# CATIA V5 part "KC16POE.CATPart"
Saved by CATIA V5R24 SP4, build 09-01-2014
Part number: KC16_AssiemeCompleto
Source: Unknown
Bounding box of the stored display mesh (mm): x 152.513 to 747.492, y 129.501 to 599, z 1609.5 to 2811.996
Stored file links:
  C:\Users\gianluca.diodoro\Desktop\Cappe 3D\KC16POE.CATPart
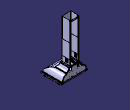
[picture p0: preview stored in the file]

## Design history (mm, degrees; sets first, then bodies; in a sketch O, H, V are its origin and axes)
Set1
  DatumSurface1 to DatumSurface402 "MANIFOLD_SOLID_BREP #451689"
Body1 "MANIFOLD_SOLID_BREP #44438" (main body)
  Solid1: solid without history
Body2 "MANIFOLD_SOLID_BREP #45255"
  Solid2: solid without history
Body3 "MANIFOLD_SOLID_BREP #57676"
  Solid3: solid without history
Body4 "MANIFOLD_SOLID_BREP #70097"
  Solid4: solid without history
Body5 "MANIFOLD_SOLID_BREP #70739"
  Solid5: solid without history
Body6 "MANIFOLD_SOLID_BREP #72519"
  Solid6: solid without history
Body7 "MANIFOLD_SOLID_BREP #73161"
  Solid7: solid without history
Body8 "MANIFOLD_SOLID_BREP #74941"
  Solid8: solid without history
Body9 "MANIFOLD_SOLID_BREP #89080"
  Solid9: solid without history
Body10 "MANIFOLD_SOLID_BREP #103211"
  Solid10: solid without history
Body11 "MANIFOLD_SOLID_BREP #106813"
  Solid11: solid without history
Body12 "MANIFOLD_SOLID_BREP #110415"
  Solid12: solid without history
Body13 "MANIFOLD_SOLID_BREP #133857"
  Solid13: solid without history
Body14 "MANIFOLD_SOLID_BREP #133987"
  Solid14: solid without history
Body15 "MANIFOLD_SOLID_BREP #140974"
  Solid15: solid without history
Body16 "MANIFOLD_SOLID_BREP #141441"
  Solid16: solid without history
Body17 "MANIFOLD_SOLID_BREP #141908"
  Solid17: solid without history
Body18 "MANIFOLD_SOLID_BREP #142375"
  Solid18: solid without history
Body19 "MANIFOLD_SOLID_BREP #142842"
  Solid19: solid without history
Body20 "MANIFOLD_SOLID_BREP #152109"
  Solid20: solid without history
Body21 "MANIFOLD_SOLID_BREP #152209"
  Solid21: solid without history
Body22 "MANIFOLD_SOLID_BREP #153280"
  Solid22: solid without history
Body23 "MANIFOLD_SOLID_BREP #154351"
  Solid23: solid without history
Body24 "MANIFOLD_SOLID_BREP #154854"
  Solid24: solid without history
Body25 "MANIFOLD_SOLID_BREP #155589"
  Solid25: solid without history
Body26 "MANIFOLD_SOLID_BREP #156092"
  Solid26: solid without history
Body27 "MANIFOLD_SOLID_BREP #156827"
  Solid27: solid without history
Body28 "MANIFOLD_SOLID_BREP #157562"
  Solid28: solid without history
Body29 "MANIFOLD_SOLID_BREP #158065"
  Solid29: solid without history
Body30 "MANIFOLD_SOLID_BREP #158800"
  Solid30: solid without history
Body31 "MANIFOLD_SOLID_BREP #159303"
  Solid31: solid without history
Body32 "MANIFOLD_SOLID_BREP #160374"
  Solid32: solid without history
Body33 "MANIFOLD_SOLID_BREP #161445"
  Solid33: solid without history
Body34 "MANIFOLD_SOLID_BREP #161545"
  Solid34: solid without history
Body35 "MANIFOLD_SOLID_BREP #162048"
  Solid35: solid without history
Body36 "MANIFOLD_SOLID_BREP #163071"
  Solid36: solid without history
Body37 "MANIFOLD_SOLID_BREP #164094"
  Solid37: solid without history
Body38 "MANIFOLD_SOLID_BREP #165117"
  Solid38: solid without history
Body39 "MANIFOLD_SOLID_BREP #166140"
  Solid39: solid without history
Body40 "MANIFOLD_SOLID_BREP #167163"
  Solid40: solid without history
Body41 "MANIFOLD_SOLID_BREP #168186"
  Solid41: solid without history
Body42 "MANIFOLD_SOLID_BREP #169209"
  Solid42: solid without history
Body43 "MANIFOLD_SOLID_BREP #170232"
  Solid43: solid without history
Body44 "MANIFOLD_SOLID_BREP #171729"
  Solid44: solid without history
Body45 "MANIFOLD_SOLID_BREP #173047"
  Solid45: solid without history
Body46 "MANIFOLD_SOLID_BREP #174431"
  Solid46: solid without history
Body47 "MANIFOLD_SOLID_BREP #175399"
  Solid47: solid without history
Body48 "MANIFOLD_SOLID_BREP #176863"
  Solid48: solid without history
Body49 "MANIFOLD_SOLID_BREP #181621"
  Solid49: solid without history
Body50 "MANIFOLD_SOLID_BREP #187015"
  Solid50: solid without history
Body51 "MANIFOLD_SOLID_BREP #411840"
  Solid51: solid without history
Body52 "MANIFOLD_SOLID_BREP #411998"
Body53 "MANIFOLD_SOLID_BREP #412156"
Body54 "MANIFOLD_SOLID_BREP #412316"
Body55 "MANIFOLD_SOLID_BREP #412474"
Body56 "MANIFOLD_SOLID_BREP #412632"
Body57 "MANIFOLD_SOLID_BREP #412790"
Body58 "MANIFOLD_SOLID_BREP #412948"
Body59 "MANIFOLD_SOLID_BREP #413106"
Body60 "MANIFOLD_SOLID_BREP #415931"
Body61 "MANIFOLD_SOLID_BREP #416093"
Body62 "MANIFOLD_SOLID_BREP #416255"
Body63 "MANIFOLD_SOLID_BREP #416417"
Body64 "MANIFOLD_SOLID_BREP #416579"
Body65 "MANIFOLD_SOLID_BREP #416741"
Body66 "MANIFOLD_SOLID_BREP #416802"
Body67 "MANIFOLD_SOLID_BREP #429679"
  Solid52: solid without history
Body68 "MANIFOLD_SOLID_BREP #439723"
  Solid53: solid without history
Body69 "MANIFOLD_SOLID_BREP #453448"
  Solid54: solid without history
Body70 "MANIFOLD_SOLID_BREP #455221"
  Solid55: solid without history
  Sketch1 on face of Solid52, origin (0, 0, 1654.9), H (1, 0, 0), V (0, -1, 0)
    line L1 (200.5023, -261.5) -> (699.5023, -261.5)
    line L2 (699.5023, -261.5) -> (699.5023, -566)
    line L3 (699.5023, -566) -> (200.5023, -566)
    line L4 (200.5023, -566) -> (200.5023, -261.5)
    reference intersected line E1 (700.5023, -568) -> (700.5023, -184) from face of Solid54
    reference intersected line E2 through (0, -260.5) direction (-1, 0) from face of Solid52
    reference intersected line E3 (199.5023, -184) -> (199.5023, -568) from face of Solid55
    reference intersected line E4 (199.5023, -567) -> (700.5023, -567) from face of Solid51
    distance E1 L2 = 1
    distance E2 L1 = 1
    distance E3 L4 = 1
    distance L3 E4 = 1
    horizontal: L1 H, L3 H
    vertical: L2 V, L4 V
  Pad1: profile Sketch1, direction (0, 0, 1), length 9
  Sketch2 on start face of Pad1, origin (0, 0, 1654.9), H (1, 0, 0), V (0, -1, 0)
    point P1 (450.0023, -261.5)
    line L1 (450.0023, -261.5) -> (450.0023, -566)
    point P2 (450.0023, -566)
    reference projected line E1 (699.5023, -261.5) -> (200.5023, -261.5) from edge [face of Pad1 from Sketch1.L1 | start face of Pad1]
    reference projected line E2 (200.5023, -566) -> (699.5023, -566) from edge [face of Pad1 from Sketch1.L3 | start face of Pad1]
    reference projected line E3 (200.5023, -261.5) -> (200.5023, -566) from edge [face of Pad1 from Sketch1.L4 | start face of Pad1]
    distance P1 E1 = 0
    distance E2 P2 = 0
    distance L1 E3 = 249.5
    vertical: L1 V
  Pocket1: profile Sketch2, direction (0, 0, 1), length 9, thin wall 1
